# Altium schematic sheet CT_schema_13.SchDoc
size 146 x 119 mm
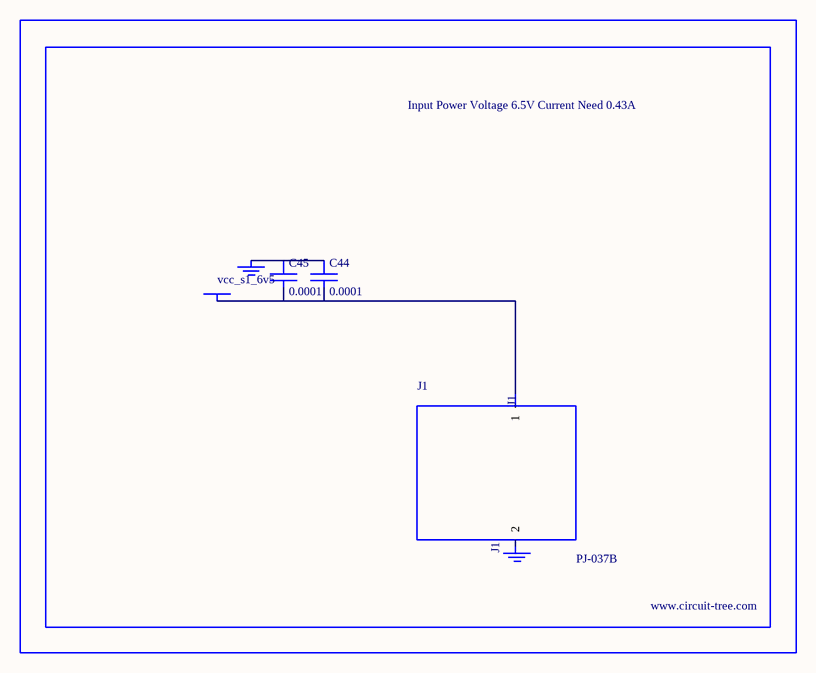
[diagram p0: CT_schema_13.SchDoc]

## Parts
BORDER12  (no value)
C44  0.0001  [EXV-9H]
C45  0.0001  [EXV-9H]
GND_INSTANCE_12_0  (no value)
GND_INSTANCE_12_1  (no value)
J1  PJ-037B  [PJ-037B_PACKAGE]
POWER_INSTANCE_12_0  vcc_s1_6v5

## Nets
NetC44_1: C44.1 C45.1 GND_INSTANCE_12_0.0(GND)
NetC44_2: C44.2 C45.2 J1.1 POWER_INSTANCE_12_0.0(PWR)

Not connected (* = marked no-connect by the designer): GND_INSTANCE_12_1 0(GND); J1 2

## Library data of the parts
BORDER12 = BORDER_PAGE12
C44 C45 = EDK107M035A9HAA
GND_INSTANCE_12_0 GND_INSTANCE_12_1 = GND
POWER_INSTANCE_12_0 = PWR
